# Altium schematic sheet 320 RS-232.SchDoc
size Letter; Organization: Toradex Solutions Inc.; Address1: 6415 Northwest Drive; Address2: Mississauga, ON, L4V 1X1; Address3: Canada
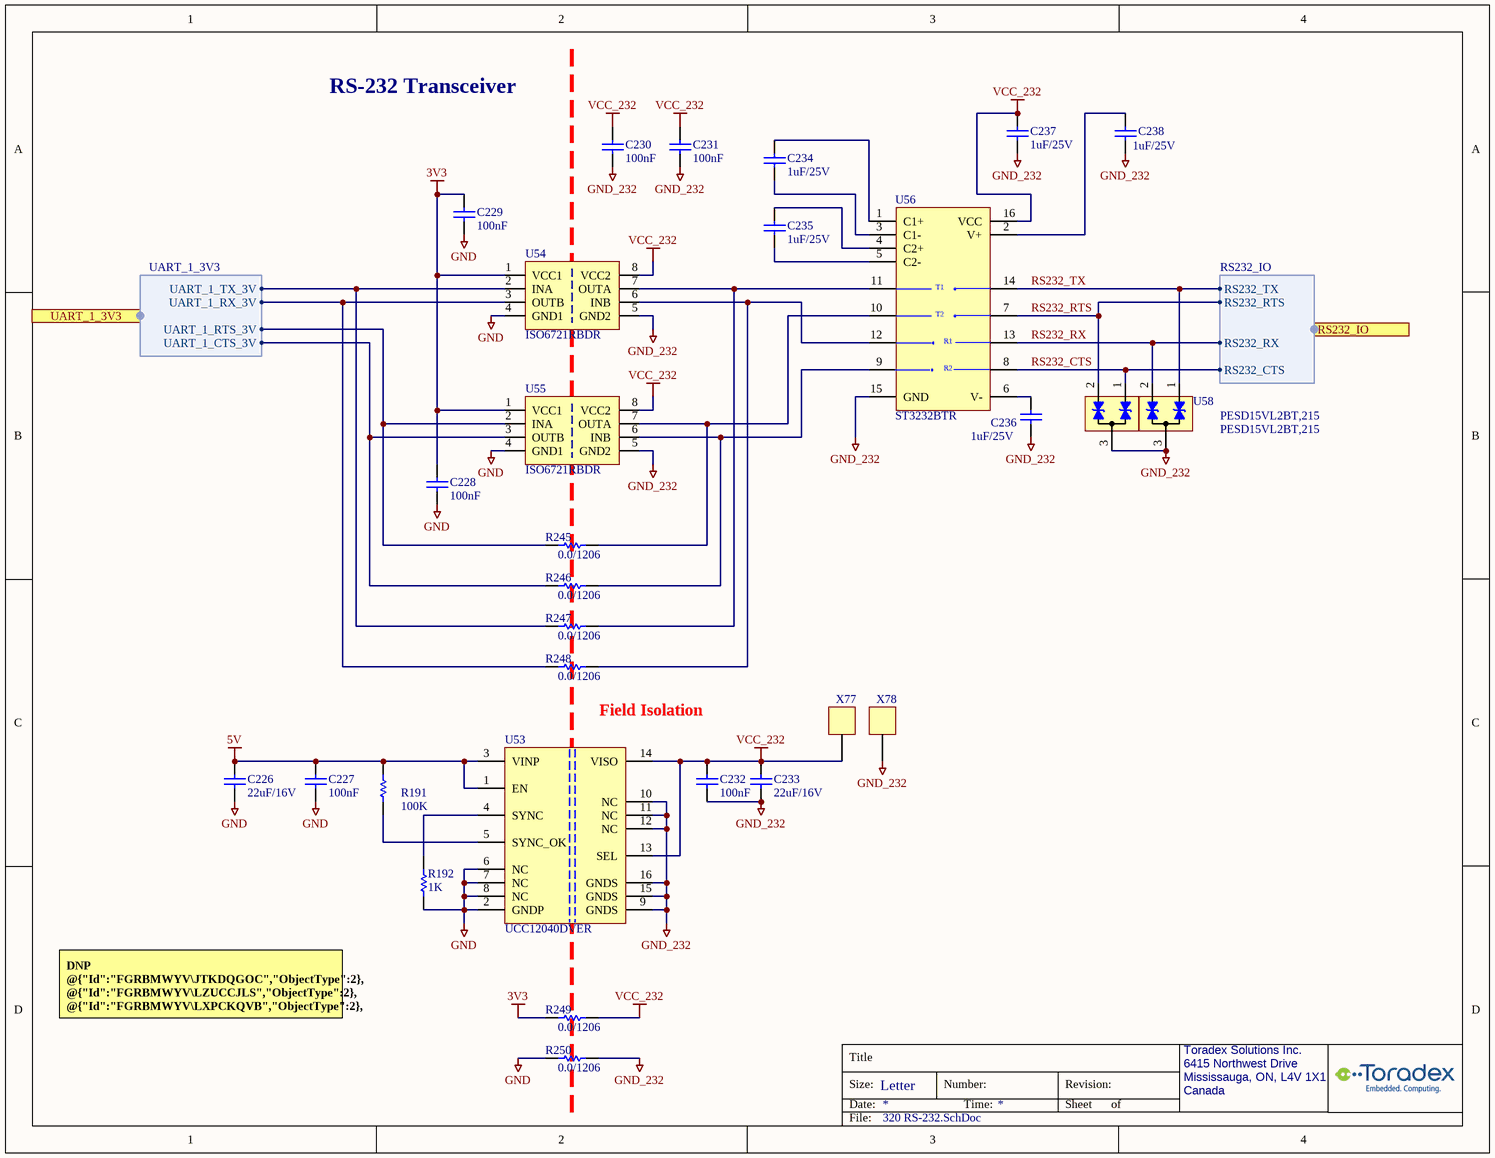
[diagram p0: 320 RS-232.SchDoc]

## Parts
C226  value 22uF/16V  [C/0805]  (hidden comment: 1314-Cap-0805-22uF/16V)
C227  100nF  [C0402_CAPC1005L]
C228  100nF  [C0402_CAPC1005L]
C229  100nF  [C0402_CAPC1005L]
C230  100nF  [C0402_CAPC1005L]
C231  100nF  [C0402_CAPC1005L]
C232  100nF  [C0402_CAPC1005L]
C233  value 22uF/16V  [C/0805]  (hidden comment: 1314-Cap-0805-22uF/16V)
C234  value 1uF/25V  [C/0603]  (hidden comment: 0124-Cap-0603-1uF/25V)
C235  value 1uF/25V  [C/0603]  (hidden comment: 0124-Cap-0603-1uF/25V)
C236  value 1uF/25V  [C/0603]  (hidden comment: 0124-Cap-0603-1uF/25V)
C237  value 1uF/25V  [C/0603]  (hidden comment: 0124-Cap-0603-1uF/25V)
C238  value 1uF/25V  [C/0603]  (hidden comment: 0124-Cap-0603-1uF/25V)
R191  value 100K  [R0402_RESC1005L]  (hidden comment: 1977-Res-0402-100K)
R192  value 1K  [R0402_RESC1005L]  (hidden comment: 1650-Res-0402-1K)
R245  value 0.0/1206  [R/1206]  (hidden comment: 0038-Res-1206-0.0ohm)
R246  value 0.0/1206  [R/1206]  (hidden comment: 0038-Res-1206-0.0ohm)
R247  value 0.0/1206  [R/1206]  (hidden comment: 0038-Res-1206-0.0ohm)
R248  value 0.0/1206  [R/1206]  (hidden comment: 0038-Res-1206-0.0ohm)
R249  value 0.0/1206  [R/1206]  (hidden comment: 0038-Res-1206-0.0ohm)
R250  value 0.0/1206  [R/1206]  (hidden comment: 0038-Res-1206-0.0ohm)
U53  UCC12040DVER  [SOIC-16]
U54  ISO6721RBDR  [SOIC-8]
U55  ISO6721RBDR  [SOIC-8]
U56  ST3232BTR  [PW016]
U57  PESD15VL2BT,215  [SOT23_N]
U58  PESD15VL2BT,215  [SOT23_N]
X77  000-TestPoint  [TestPoint_1]  (value not drawn)
X78  000-TestPoint  [TestPoint_1]  (value not drawn)

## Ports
RS232_IO (harness RS232_IO), UART_1_3V3 (harness UART_1_3V3)

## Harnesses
UART_1_3V3: UART_1_RX_3V, UART_1_TX_3V, UART_1_RTS_3V, UART_1_CTS_3V
RS232_IO: RS232_RX, RS232_CTS, RS232_TX, RS232_RTS

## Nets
3V3: C228.1 C229.1 R249.2 U54.1(VCC1) U55.1(VCC1)
5V: C226.2 C227.1 R191.2 U53.1(EN) U53.3(VINP)
GND: C226.1 C227.2 C228.2 C229.2 R192.1 R250.2 U53.2(GNDP) U53.6(NC) U53.7(NC) U53.8(NC) U54.4(GND1) U55.4(GND1)
GND_232: C230.2 C231.2 C232.2 C233.1 C236.1 C237.1 C238.1 R250.1 U53.9(GNDS) U53.10(NC) U53.11(NC) U53.12(NC) U53.15(GNDS) U53.16(GNDS) U54.5(GND2) U55.5(GND2) U56.15(GND) U57.3(CC) U58.3(CC) X78.1
VCC_232: C230.1 C231.1 C232.1 C233.2 C237.2 R249.1 U53.13(SEL) U53.14(VISO) U54.8(VCC2) U55.8(VCC2) U56.16(VCC) X77.1
RS232_CTS: U56.8(R2IN) U57.1(K1) ; port RS232_IO.RS232_CTS
RS232_RTS: U56.7(T2OUT) U57.2(K2) ; port RS232_IO.RS232_RTS
RS232_RX: U56.13(R1IN) U58.2(K2) ; port RS232_IO.RS232_RX
RS232_TX: U56.14(T1OUT) U58.1(K1) ; port RS232_IO.RS232_TX
NetC234_1: C234.1 U56.3(C1-)
NetC234_2: C234.2 U56.1(C1+)
NetC235_1: C235.1 U56.5(C2-)
NetC235_2: C235.2 U56.4(C2+)
NetC236_2: C236.2 U56.6(V-)
NetC238_2: C238.2 U56.2(V+)
NetR191_1: R191.1 U53.5(SYNC_OK)
NetR192_2: R192.2 U53.4(SYNC)
NetR245_1: R245.1 U55.7(OUTA) U56.10(T2IN)
NetR245_2: R245.2 U55.2(INA) ; port UART_1_3V3.UART_1_RTS_3V
NetR246_1: R246.1 U55.6(INB) U56.9(R2OUT)
NetR246_2: R246.2 U55.3(OUTB) ; port UART_1_3V3.UART_1_CTS_3V
NetR247_1: R247.1 U54.7(OUTA) U56.11(T1IN)
NetR247_2: R247.2 U54.2(INA) ; port UART_1_3V3.UART_1_TX_3V
NetR248_1: R248.1 U54.6(INB) U56.12(R1OUT)
NetR248_2: R248.2 U54.3(OUTB) ; port UART_1_3V3.UART_1_RX_3V

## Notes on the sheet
- RS-232 Transceiver
- Field Isolation
- DNP @{"Id":"FGRBMWYV\JTKDQGOC","ObjectType":2}, @{"Id":"FGRBMWYV\LZUCCJLS","ObjectType":2}, @{"Id":"FGRBMWYV\LXPCKQVB","ObjectType":2}, @{"Id":"FGRBMWYV\FLONWOHB","ObjectType":2}, @{"Id":"FGRBMWYV\YEYATVRD","ObjectType":2}, @{"Id":"FGRBMWYV\DSLTWDMJ","ObjectType":2} are bypass jumpers when @{"Id":"FGRBMWYV\LXYJYHOV"}, @{"Id":"FGRBMWYV\GHWLQOMO"} and @{"Id":"FGRBMWYV\XDAZDTFI"} aren't mounted.

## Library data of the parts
C226 C233 = 1314-Cap-0805-22uF/16V: (-55 to 85 DegC) CAP CER 22uF 16V X5R 0805; MfrNo: CL21A226MOQNNNE; Mfr: Samsung; PN: 1314; Alt: CL21A226MOCLRNC,CL21A226KOQNNNG,GRM21BR61C226ME44L,EMK212BBJ226MG-T
C227-C232 = 1566-Cap-0402-100nF/50V: (-55 to 125 DegC AEC) Cap Ceramic 0.1uF 50V X7R 10% 0402; MfrNo: GRT155R71H104KE01D; Mfr: Murata; Alt: CL05B104KB54PNC,GCM155R71H104ME02D,GCM155R71H104KE02D,GCM155R71H104KE02J; PN: 1566
C234-C238 = 0124-Cap-0603-1uF/25V: CAP CER 1UF 25V 10% X5R 0603; Mfr: Yageo; MfrNo: CC0603KRX5R8BB105; Alt: 587-1248-1-ND; Alt2: 587-2984-1-ND; PN: 124
R191 = 1977-Res-0402-100K: (-55 to 155 DegC) RES 100K OHM 1/16W 1% 0402 SMD; Mfr: Yageo; MfrNo: RC0402FR-07100KL; PN: 1977
R192 = 1650-Res-0402-1K: (-55 to 155 DegC AEC) RES 1K OHM 1% 1/16W 100ppm 0402; Mfr: TE Connectivity; MfrNo: CRGCQ0402F1K0; PN: 1650; Alt: CR0402AFX-1001GLF,AC0402FR-131KL,AC0402FR-071KL
R245-R250 = 0038-Res-1206-0.0ohm: (-55 to 155 DegC) RES 0.0 OHM 1/4W JUMPER 1206; Mfr: TE; MfrNo: 1623693-1; PN: 38; Alt: 311-0.0ERCT-ND; Alt2: RMCF1206ZT0R00CT-ND
U53 = 2065-UCC12040DVER: (-40 to 125 DegC) IC Isolated DC DC Converter-Output 3.3V, 5V 140mA, 4.5V-5.5V Input; Mfr: Texas Instruments; PN: 2065
U54 U55 = 2198-ISO6721RBDR: (-40 to 125 DegC) IC DGTL ISO GENERAL-PURPOSE, DUAL-CHANNEL, 1x In, 1x Out 1.71-5.5V; Mfr: Texas Instruments; PN: 2198
U56 = 0156-ST3232BTR: IC DRVR/RCVR RS232 LP 16-TSSOP; Mfr: ST; Alt: 296-13100-1-ND; Alt2: 296-23467-1-ND; PN: 156; TR: 497-6534-2-ND; DR: 497-6534-6-ND; DR2: 511-ST3232BT
U57 U58 = 2239-PESD15VL2BT,215: (-65 to 150 DegC) TVS DIODE 2-CH 15VWM 44VC ESD:30KV TO236AB; Mfr: Nexperia; PN: 2239
X77 X78 = 000-TestPoint: Note: this is PCB footprint only, no parts to buy or assemble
